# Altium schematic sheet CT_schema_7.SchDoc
size 277 x 170 mm
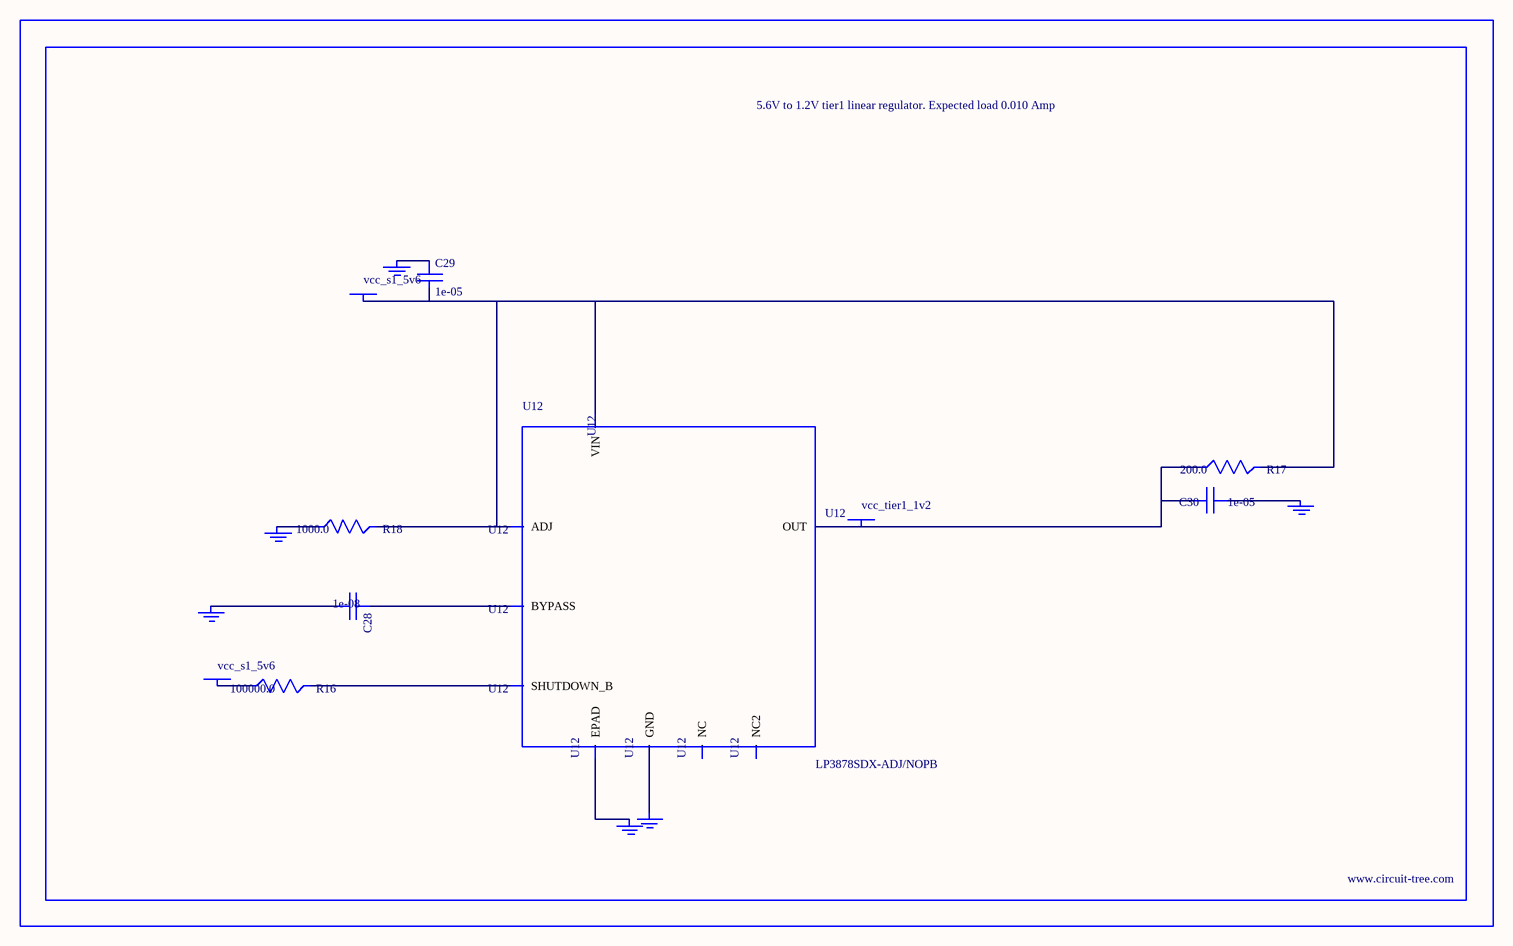
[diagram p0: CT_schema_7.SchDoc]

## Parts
BORDER6  (no value)
C28  1e-08  [C0402]
C29  1e-05  [C1206]
C30  1e-05  [C0805]
GND_INSTANCE_6_0  (no value)
GND_INSTANCE_6_1  (no value)
GND_INSTANCE_6_2  (no value)
GND_INSTANCE_6_3  (no value)
GND_INSTANCE_6_4  (no value)
GND_INSTANCE_6_5  (no value)
POWER_INSTANCE_6_0  vcc_s1_5v6
POWER_INSTANCE_6_1  vcc_s1_5v6
POWER_INSTANCE_6_2  vcc_tier1_1v2
R16  100000.0  [R0603]
R17  200.0  [R0603]
R18  1000.0  [R0603]
U12  LP3878SDX-ADJ/NOPB  [WSON-8]

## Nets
NetC28_1: C28.1 U12.1(BYPASS)
NetC28_2: C28.2 GND_INSTANCE_6_0.0(GND)
NetC29_1: C29.1 GND_INSTANCE_6_1.0(GND)
NetC29_2: C29.2 POWER_INSTANCE_6_0.0(PWR) R17.2 R18.2 U12.4(VIN) U12.6(ADJ)
NetC30_1: C30.1 GND_INSTANCE_6_2.0(GND)
NetC30_2: C30.2 POWER_INSTANCE_6_2.0(PWR) R17.1 U12.5(OUT)
NetGND_INSTANCE_6_3_0: GND_INSTANCE_6_3.0(GND) R18.1
NetGND_INSTANCE_6_4_0: GND_INSTANCE_6_4.0(GND) U12.PAD(EPAD)
NetGND_INSTANCE_6_5_0: GND_INSTANCE_6_5.0(GND) U12.3(GND)
NetPOWER_INSTANCE_6_1_0: POWER_INSTANCE_6_1.0(PWR) R16.1
NetR16_2: R16.2 U12.8(SHUTDOWN_B)

Not connected (* = marked no-connect by the designer): U12 2(NC) 7(NC2)

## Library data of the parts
BORDER6 = BORDER_PAGE6
C28 = C0402C103K3RAC
C29 = C1206C106K3RACTU
C30 = GRM219R60J106ME19D
GND_INSTANCE_6_0-GND_INSTANCE_6_5 = GND
POWER_INSTANCE_6_0-POWER_INSTANCE_6_2 = PWR
R16 = RC0603JR-07100KL
R17 = RC0603JR-07200RL
R18 = RC0603JR-071KL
